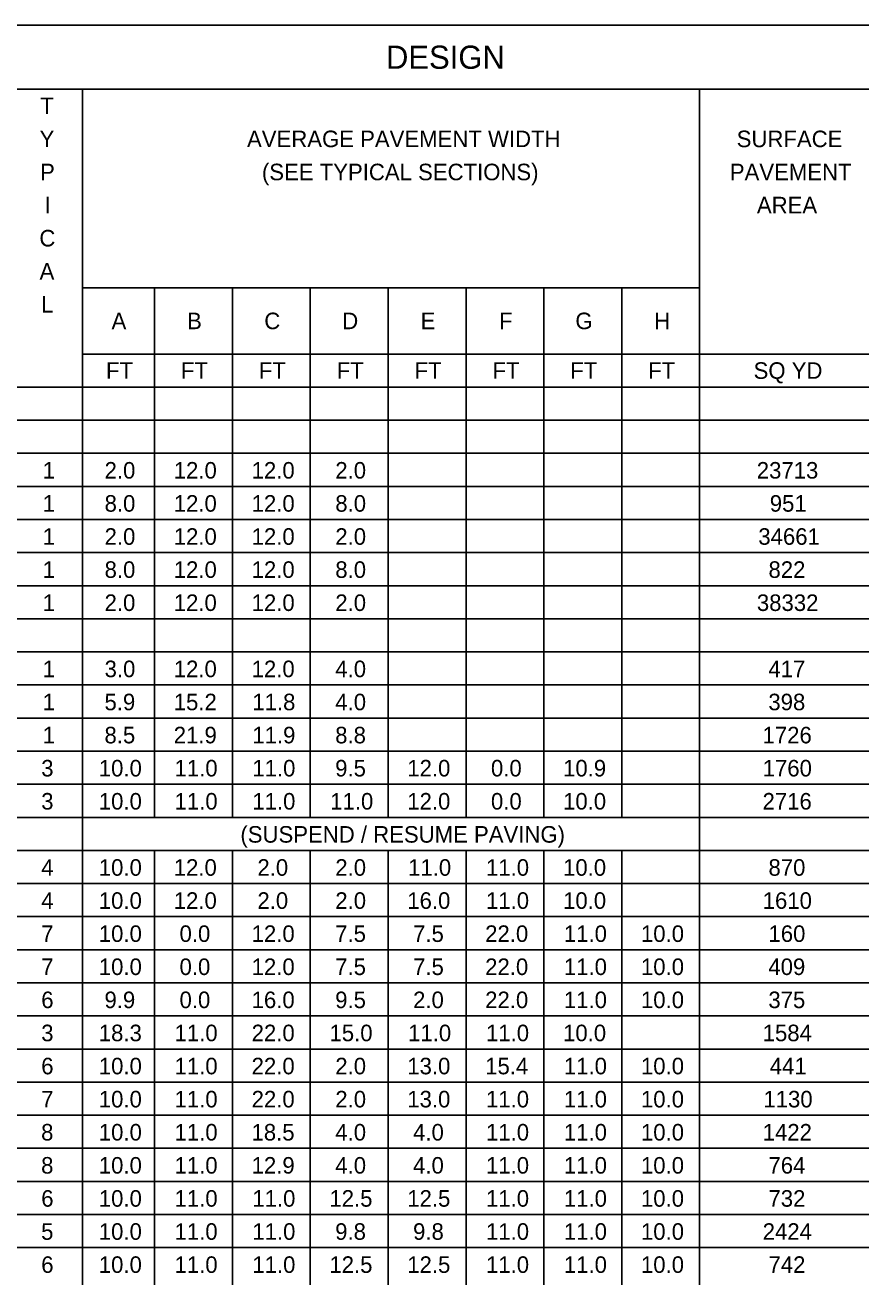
# Model space of a CAD drawing. Extents: x 12522 to 13018, y 1124 to 1902.
# Drawn here: x 12805.7 to 12812.77, y 1815.06 to 1825.65 of the extents above; entities that cross this region are included whole.
import ezdxf

# ---------------------------------------------------------------- set-up
doc = ezdxf.new("R2010")
doc.units = 0
for name, color, linetype in [('SC_Scratch1', 7, 'Continuous'), ('SH_Data', 7, 'Continuous'), ('SH_Text', 7, 'Continuous')]:
    doc.layers.add(name, color=color, linetype=linetype)

msp = doc.modelspace()

# ---------------------------------------------------------------- linework, layer by layer
at = {"layer": 'SC_Scratch1'}
msp.add_lwpolyline([(12797.224, 1825.65), (12827.724, 1825.65), (12827.724, 1804.65), (12797.224, 1804.65)], close=True, dxfattribs=at)
at = {"layer": 'SH_Data'}
for p, q in [((12797.224, 1825.107), (12827.678, 1825.107)), ((12806.184, 1825.107), (12806.184, 1805.227)), ((12811.405, 1825.107), (12811.405, 1805.227)), ((12806.184, 1823.427), (12811.405, 1823.427)), ((12806.794, 1823.427), (12806.794, 1818.947)), ((12807.452, 1823.427), (12807.452, 1818.947)), ((12808.111, 1823.427), (12808.111, 1818.947)), ((12808.77, 1823.427), (12808.77, 1818.947)), ((12809.429, 1823.427), (12809.429, 1818.947)), ((12810.088, 1823.427), (12810.088, 1818.947)), ((12810.747, 1823.427), (12810.747, 1818.947)), ((12806.184, 1822.867), (12827.678, 1822.867)), ((12797.224, 1822.587), (12827.678, 1822.587)), ((12797.224, 1822.307), (12827.678, 1822.307)), ((12797.224, 1822.027), (12827.678, 1822.027)), ((12797.224, 1821.747), (12827.678, 1821.747)), ((12797.224, 1821.467), (12827.678, 1821.467)), ((12797.224, 1821.187), (12827.678, 1821.187)), ((12797.224, 1820.907), (12827.678, 1820.907)), ((12797.224, 1820.627), (12827.678, 1820.627)), ((12797.224, 1820.347), (12827.678, 1820.347)), ((12797.224, 1820.067), (12827.678, 1820.067)), ((12797.224, 1819.787), (12827.678, 1819.787)), ((12797.224, 1819.507), (12827.678, 1819.507)), ((12797.224, 1819.227), (12827.678, 1819.227)), ((12797.224, 1818.947), (12827.678, 1818.947)), ((12797.224, 1818.667), (12827.678, 1818.667)), ((12806.794, 1818.667), (12806.794, 1805.227)), ((12807.452, 1818.667), (12807.452, 1805.227)), ((12808.111, 1818.667), (12808.111, 1805.227)), ((12808.77, 1818.667), (12808.77, 1805.227)), ((12809.429, 1818.667), (12809.429, 1805.227)), ((12810.088, 1818.667), (12810.088, 1805.227)), ((12810.747, 1818.667), (12810.747, 1805.227)), ((12797.224, 1818.387), (12827.678, 1818.387)), ((12797.224, 1818.107), (12827.678, 1818.107)), ((12797.224, 1817.827), (12827.678, 1817.827)), ((12797.224, 1817.547), (12827.678, 1817.547)), ((12797.224, 1817.267), (12827.678, 1817.267)), ((12797.224, 1816.987), (12827.678, 1816.987)), ((12797.224, 1816.707), (12827.678, 1816.707)), ((12797.224, 1816.427), (12827.678, 1816.427)), ((12797.224, 1816.147), (12827.678, 1816.147)), ((12797.224, 1815.867), (12827.678, 1815.867)), ((12797.224, 1815.587), (12827.678, 1815.587)), ((12797.224, 1815.307), (12827.678, 1815.307))]:
    msp.add_line(p, q, dxfattribs=at)

# ---------------------------------------------------------------- texts
at = {"layer": 'SH_Text'}
for s, height, p in [('DESIGN', 0.196, (12808.752, 1825.28)), ('T', 0.14, (12805.827, 1824.897)), ('Y', 0.14, (12805.821, 1824.617)), ('AVERAGE PAVEMENT WIDTH', 0.14, (12807.576, 1824.617)), ('SURFACE', 0.14, (12811.719, 1824.617)), ('P', 0.14, (12805.825, 1824.337)), ('(SEE TYPICAL SECTIONS)', 0.14, (12807.702, 1824.337)), ('PAVEMENT', 0.14, (12811.661, 1824.337)), ('I', 0.14, (12805.863, 1824.057)), ('AREA', 0.14, (12811.89, 1824.057)), ('C', 0.14, (12805.819, 1823.777)), ('A', 0.14, (12805.821, 1823.497)), ('L', 0.14, (12805.834, 1823.217)), ('A', 0.14, (12806.43, 1823.077)), ('B', 0.14, (12807.069, 1823.077)), ('C', 0.14, (12807.722, 1823.077)), ('D', 0.14, (12808.382, 1823.077)), ('E', 0.14, (12809.045, 1823.077)), ('F', 0.14, (12809.709, 1823.077)), ('G', 0.14, (12810.354, 1823.077)), ('H', 0.14, (12811.02, 1823.077)), ('FT', 0.14, (12806.383, 1822.657)), ('FT', 0.14, (12807.017, 1822.657)), ('FT', 0.14, (12807.676, 1822.657)), ('FT', 0.14, (12808.335, 1822.657)), ('FT', 0.14, (12808.994, 1822.657)), ('FT', 0.14, (12809.653, 1822.657)), ('FT', 0.14, (12810.311, 1822.657)), ('FT', 0.14, (12810.97, 1822.657)), ('SQ YD', 0.14, (12811.862, 1822.657)), ('1', 0.14, (12805.847, 1821.813)), ('2.0', 0.14, (12806.371, 1821.813)), ('12.0', 0.14, (12806.956, 1821.813)), ('12.0', 0.14, (12807.615, 1821.813)), ('2.0', 0.14, (12808.323, 1821.813)), ('23713', 0.14, (12811.889, 1821.813)), ('1', 0.14, (12805.847, 1821.533)), ('8.0', 0.14, (12806.371, 1821.533)), ('12.0', 0.14, (12806.956, 1821.533)), ('12.0', 0.14, (12807.615, 1821.533)), ('8.0', 0.14, (12808.323, 1821.533)), ('951', 0.14, (12811.999, 1821.533)), ('1', 0.14, (12805.847, 1821.253)), ('2.0', 0.14, (12806.371, 1821.253)), ('12.0', 0.14, (12806.956, 1821.253)), ('12.0', 0.14, (12807.615, 1821.253)), ('2.0', 0.14, (12808.323, 1821.253)), ('34661', 0.14, (12811.902, 1821.253)), ('1', 0.14, (12805.847, 1820.973)), ('8.0', 0.14, (12806.371, 1820.973)), ('12.0', 0.14, (12806.956, 1820.973)), ('12.0', 0.14, (12807.615, 1820.973)), ('8.0', 0.14, (12808.323, 1820.973)), ('822', 0.14, (12811.988, 1820.973)), ('1', 0.14, (12805.847, 1820.693)), ('2.0', 0.14, (12806.371, 1820.693)), ('12.0', 0.14, (12806.956, 1820.693)), ('12.0', 0.14, (12807.615, 1820.693)), ('2.0', 0.14, (12808.323, 1820.693)), ('38332', 0.14, (12811.89, 1820.693)), ('1', 0.14, (12805.847, 1820.133)), ('3.0', 0.14, (12806.371, 1820.133)), ('12.0', 0.14, (12806.956, 1820.133)), ('12.0', 0.14, (12807.615, 1820.133)), ('4.0', 0.14, (12808.323, 1820.133)), ('417', 0.14, (12811.987, 1820.133)), ('1', 0.14, (12805.847, 1819.853)), ('5.9', 0.14, (12806.37, 1819.853)), ('15.2', 0.14, (12806.956, 1819.853)), ('11.8', 0.14, (12807.621, 1819.853)), ('4.0', 0.14, (12808.323, 1819.853)), ('398', 0.14, (12811.987, 1819.853)), ('1', 0.14, (12805.847, 1819.573)), ('8.5', 0.14, (12806.37, 1819.573)), ('21.9', 0.14, (12806.956, 1819.573)), ('11.9', 0.14, (12807.621, 1819.573)), ('8.8', 0.14, (12808.322, 1819.573)), ('1726', 0.14, (12811.938, 1819.573)), ('3', 0.14, (12805.835, 1819.293)), ('10.0', 0.14, (12806.322, 1819.293)), ('11.0', 0.14, (12806.963, 1819.293)), ('11.0', 0.14, (12807.621, 1819.293)), ('9.5', 0.14, (12808.322, 1819.293)), ('12.0', 0.14, (12808.932, 1819.293)), ('0.0', 0.14, (12809.64, 1819.293)), ('10.9', 0.14, (12810.25, 1819.293)), ('1760', 0.14, (12811.939, 1819.293)), ('3', 0.14, (12805.835, 1819.013)), ('10.0', 0.14, (12806.322, 1819.013)), ('11.0', 0.14, (12806.963, 1819.013)), ('11.0', 0.14, (12807.621, 1819.013)), ('11.0', 0.14, (12808.28, 1819.013)), ('12.0', 0.14, (12808.932, 1819.013)), ('0.0', 0.14, (12809.64, 1819.013)), ('10.0', 0.14, (12810.25, 1819.013)), ('2716', 0.14, (12811.938, 1819.013)), ('(SUSPEND / RESUME PAVING)', 0.14, (12807.52, 1818.733)), ('4', 0.14, (12805.835, 1818.453)), ('10.0', 0.14, (12806.322, 1818.453)), ('12.0', 0.14, (12806.956, 1818.453)), ('2.0', 0.14, (12807.664, 1818.453)), ('2.0', 0.14, (12808.323, 1818.453)), ('11.0', 0.14, (12808.939, 1818.453)), ('11.0', 0.14, (12809.598, 1818.453)), ('10.0', 0.14, (12810.25, 1818.453)), ('870', 0.14, (12811.988, 1818.453)), ('4', 0.14, (12805.835, 1818.173)), ('10.0', 0.14, (12806.322, 1818.173)), ('12.0', 0.14, (12806.956, 1818.173)), ('2.0', 0.14, (12807.664, 1818.173)), ('2.0', 0.14, (12808.323, 1818.173)), ('16.0', 0.14, (12808.932, 1818.173)), ('11.0', 0.14, (12809.598, 1818.173)), ('10.0', 0.14, (12810.25, 1818.173)), ('1610', 0.14, (12811.939, 1818.173)), ('7', 0.14, (12805.835, 1817.893)), ('10.0', 0.14, (12806.322, 1817.893)), ('0.0', 0.14, (12807.005, 1817.893)), ('12.0', 0.14, (12807.615, 1817.893)), ('7.5', 0.14, (12808.322, 1817.893)), ('7.5', 0.14, (12808.981, 1817.893)), ('22.0', 0.14, (12809.591, 1817.893)), ('11.0', 0.14, (12810.257, 1817.893)), ('10.0', 0.14, (12810.909, 1817.893)), ('160', 0.14, (12811.988, 1817.893)), ('7', 0.14, (12805.835, 1817.613)), ('10.0', 0.14, (12806.322, 1817.613)), ('0.0', 0.14, (12807.005, 1817.613)), ('12.0', 0.14, (12807.615, 1817.613)), ('7.5', 0.14, (12808.322, 1817.613)), ('7.5', 0.14, (12808.981, 1817.613)), ('22.0', 0.14, (12809.591, 1817.613)), ('11.0', 0.14, (12810.257, 1817.613)), ('10.0', 0.14, (12810.909, 1817.613)), ('409', 0.14, (12811.987, 1817.613)), ('6', 0.14, (12805.835, 1817.333)), ('9.9', 0.14, (12806.37, 1817.333)), ('0.0', 0.14, (12807.005, 1817.333)), ('16.0', 0.14, (12807.615, 1817.333)), ('9.5', 0.14, (12808.322, 1817.333)), ('2.0', 0.14, (12808.981, 1817.333)), ('22.0', 0.14, (12809.591, 1817.333)), ('11.0', 0.14, (12810.257, 1817.333)), ('10.0', 0.14, (12810.909, 1817.333)), ('375', 0.14, (12811.987, 1817.333)), ('3', 0.14, (12805.835, 1817.053)), ('18.3', 0.14, (12806.322, 1817.053)), ('11.0', 0.14, (12806.963, 1817.053)), ('22.0', 0.14, (12807.615, 1817.053)), ('15.0', 0.14, (12808.274, 1817.053)), ('11.0', 0.14, (12808.939, 1817.053)), ('11.0', 0.14, (12809.598, 1817.053)), ('10.0', 0.14, (12810.25, 1817.053)), ('1584', 0.14, (12811.939, 1817.053)), ('6', 0.14, (12805.835, 1816.773)), ('10.0', 0.14, (12806.322, 1816.773)), ('11.0', 0.14, (12806.963, 1816.773)), ('22.0', 0.14, (12807.615, 1816.773)), ('2.0', 0.14, (12808.323, 1816.773)), ('13.0', 0.14, (12808.932, 1816.773)), ('15.4', 0.14, (12809.591, 1816.773)), ('11.0', 0.14, (12810.257, 1816.773)), ('10.0', 0.14, (12810.909, 1816.773)), ('441', 0.14, (12811.999, 1816.773)), ('7', 0.14, (12805.835, 1816.493)), ('10.0', 0.14, (12806.322, 1816.493)), ('11.0', 0.14, (12806.963, 1816.493)), ('22.0', 0.14, (12807.615, 1816.493)), ('2.0', 0.14, (12808.323, 1816.493)), ('13.0', 0.14, (12808.932, 1816.493)), ('11.0', 0.14, (12809.598, 1816.493)), ('11.0', 0.14, (12810.257, 1816.493)), ('10.0', 0.14, (12810.909, 1816.493)), ('1130', 0.14, (12811.945, 1816.493)), ('8', 0.14, (12805.834, 1816.213)), ('10.0', 0.14, (12806.322, 1816.213)), ('11.0', 0.14, (12806.963, 1816.213)), ('18.5', 0.14, (12807.614, 1816.213)), ('4.0', 0.14, (12808.323, 1816.213)), ('4.0', 0.14, (12808.981, 1816.213)), ('11.0', 0.14, (12809.598, 1816.213)), ('11.0', 0.14, (12810.257, 1816.213)), ('10.0', 0.14, (12810.909, 1816.213)), ('1422', 0.14, (12811.939, 1816.213)), ('8', 0.14, (12805.834, 1815.933)), ('10.0', 0.14, (12806.322, 1815.933)), ('11.0', 0.14, (12806.963, 1815.933)), ('12.9', 0.14, (12807.615, 1815.933)), ('4.0', 0.14, (12808.323, 1815.933)), ('4.0', 0.14, (12808.981, 1815.933)), ('11.0', 0.14, (12809.598, 1815.933)), ('11.0', 0.14, (12810.257, 1815.933)), ('10.0', 0.14, (12810.909, 1815.933)), ('764', 0.14, (12811.988, 1815.933)), ('6', 0.14, (12805.835, 1815.653)), ('10.0', 0.14, (12806.322, 1815.653)), ('11.0', 0.14, (12806.963, 1815.653)), ('11.0', 0.14, (12807.621, 1815.653)), ('12.5', 0.14, (12808.273, 1815.653)), ('12.5', 0.14, (12808.932, 1815.653)), ('11.0', 0.14, (12809.598, 1815.653)), ('11.0', 0.14, (12810.257, 1815.653)), ('10.0', 0.14, (12810.909, 1815.653)), ('732', 0.14, (12811.988, 1815.653)), ('5', 0.14, (12805.834, 1815.373)), ('10.0', 0.14, (12806.322, 1815.373)), ('11.0', 0.14, (12806.963, 1815.373)), ('11.0', 0.14, (12807.621, 1815.373)), ('9.8', 0.14, (12808.322, 1815.373)), ('9.8', 0.14, (12808.981, 1815.373)), ('11.0', 0.14, (12809.598, 1815.373)), ('11.0', 0.14, (12810.257, 1815.373)), ('10.0', 0.14, (12810.909, 1815.373)), ('2424', 0.14, (12811.939, 1815.373)), ('6', 0.14, (12805.835, 1815.093)), ('10.0', 0.14, (12806.322, 1815.093)), ('11.0', 0.14, (12806.963, 1815.093)), ('11.0', 0.14, (12807.621, 1815.093)), ('12.5', 0.14, (12808.273, 1815.093)), ('12.5', 0.14, (12808.932, 1815.093)), ('11.0', 0.14, (12809.598, 1815.093)), ('11.0', 0.14, (12810.257, 1815.093)), ('10.0', 0.14, (12810.909, 1815.093)), ('742', 0.14, (12811.988, 1815.093))]:
    msp.add_text(s, height=height, dxfattribs=at).set_placement(p)

doc.saveas('drawing.dxf')
